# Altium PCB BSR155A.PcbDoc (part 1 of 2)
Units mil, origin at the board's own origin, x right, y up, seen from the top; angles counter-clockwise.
Board outline 3250 x 2500 mil, 4 copper layers (Top Layer, MidLayer1, MidLayer2, Bottom Layer), stack 59.8 mil thick; 70 components, 25 nets, 149 pads, 70 vias.
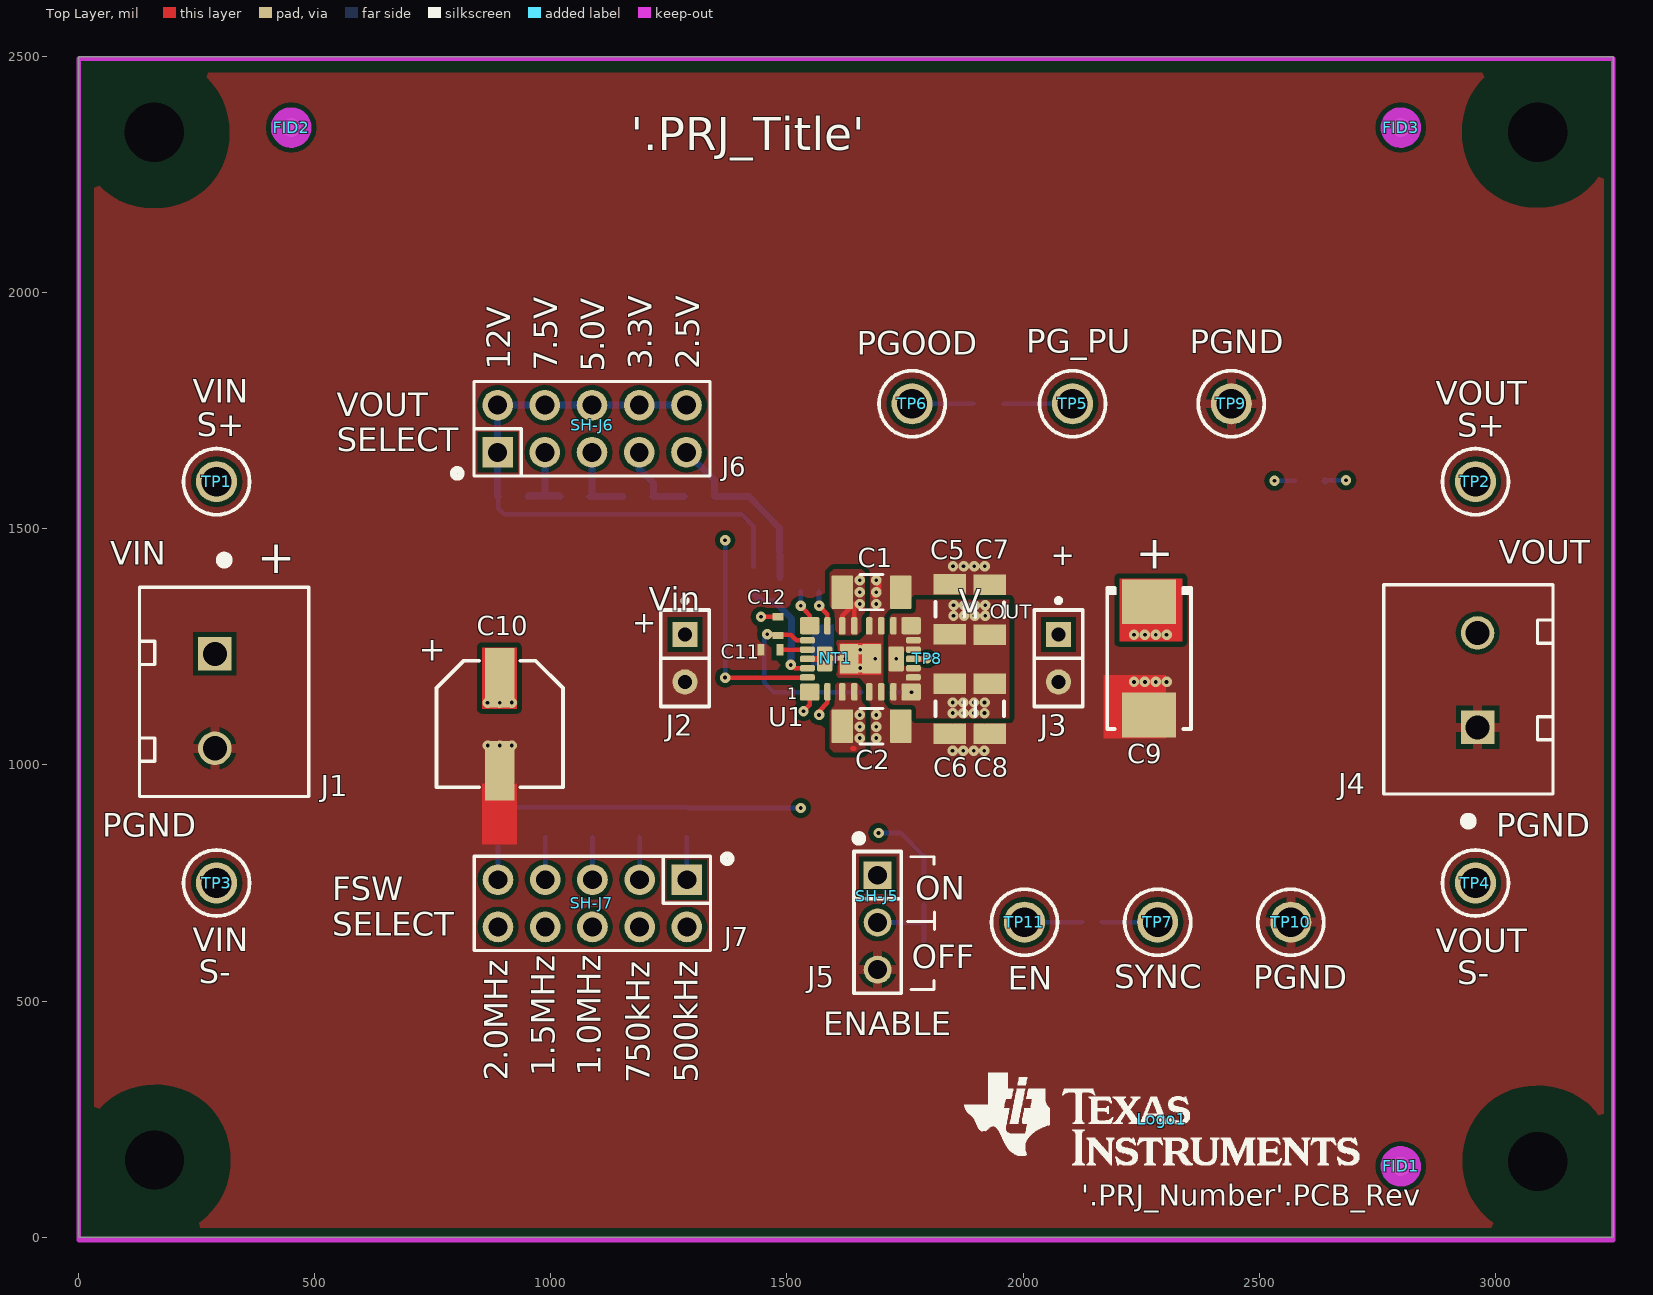
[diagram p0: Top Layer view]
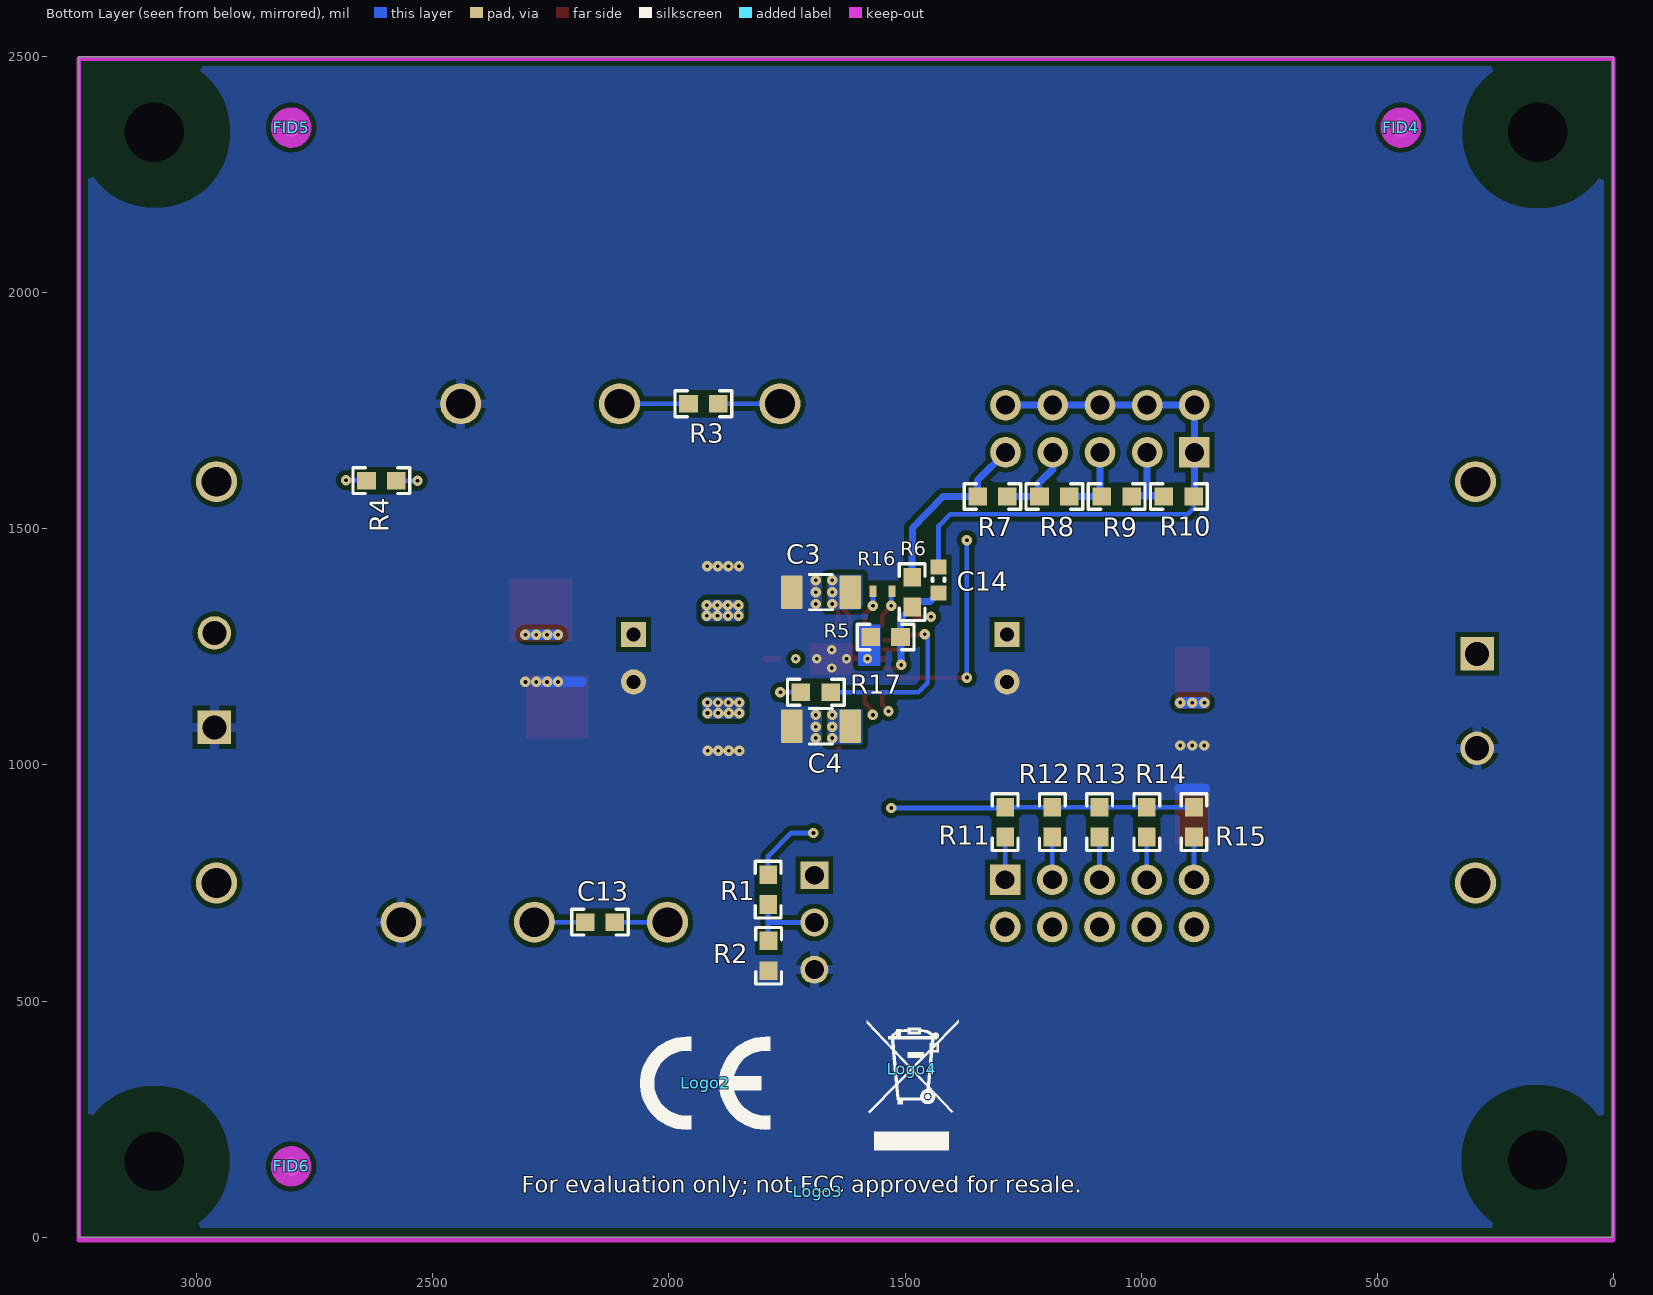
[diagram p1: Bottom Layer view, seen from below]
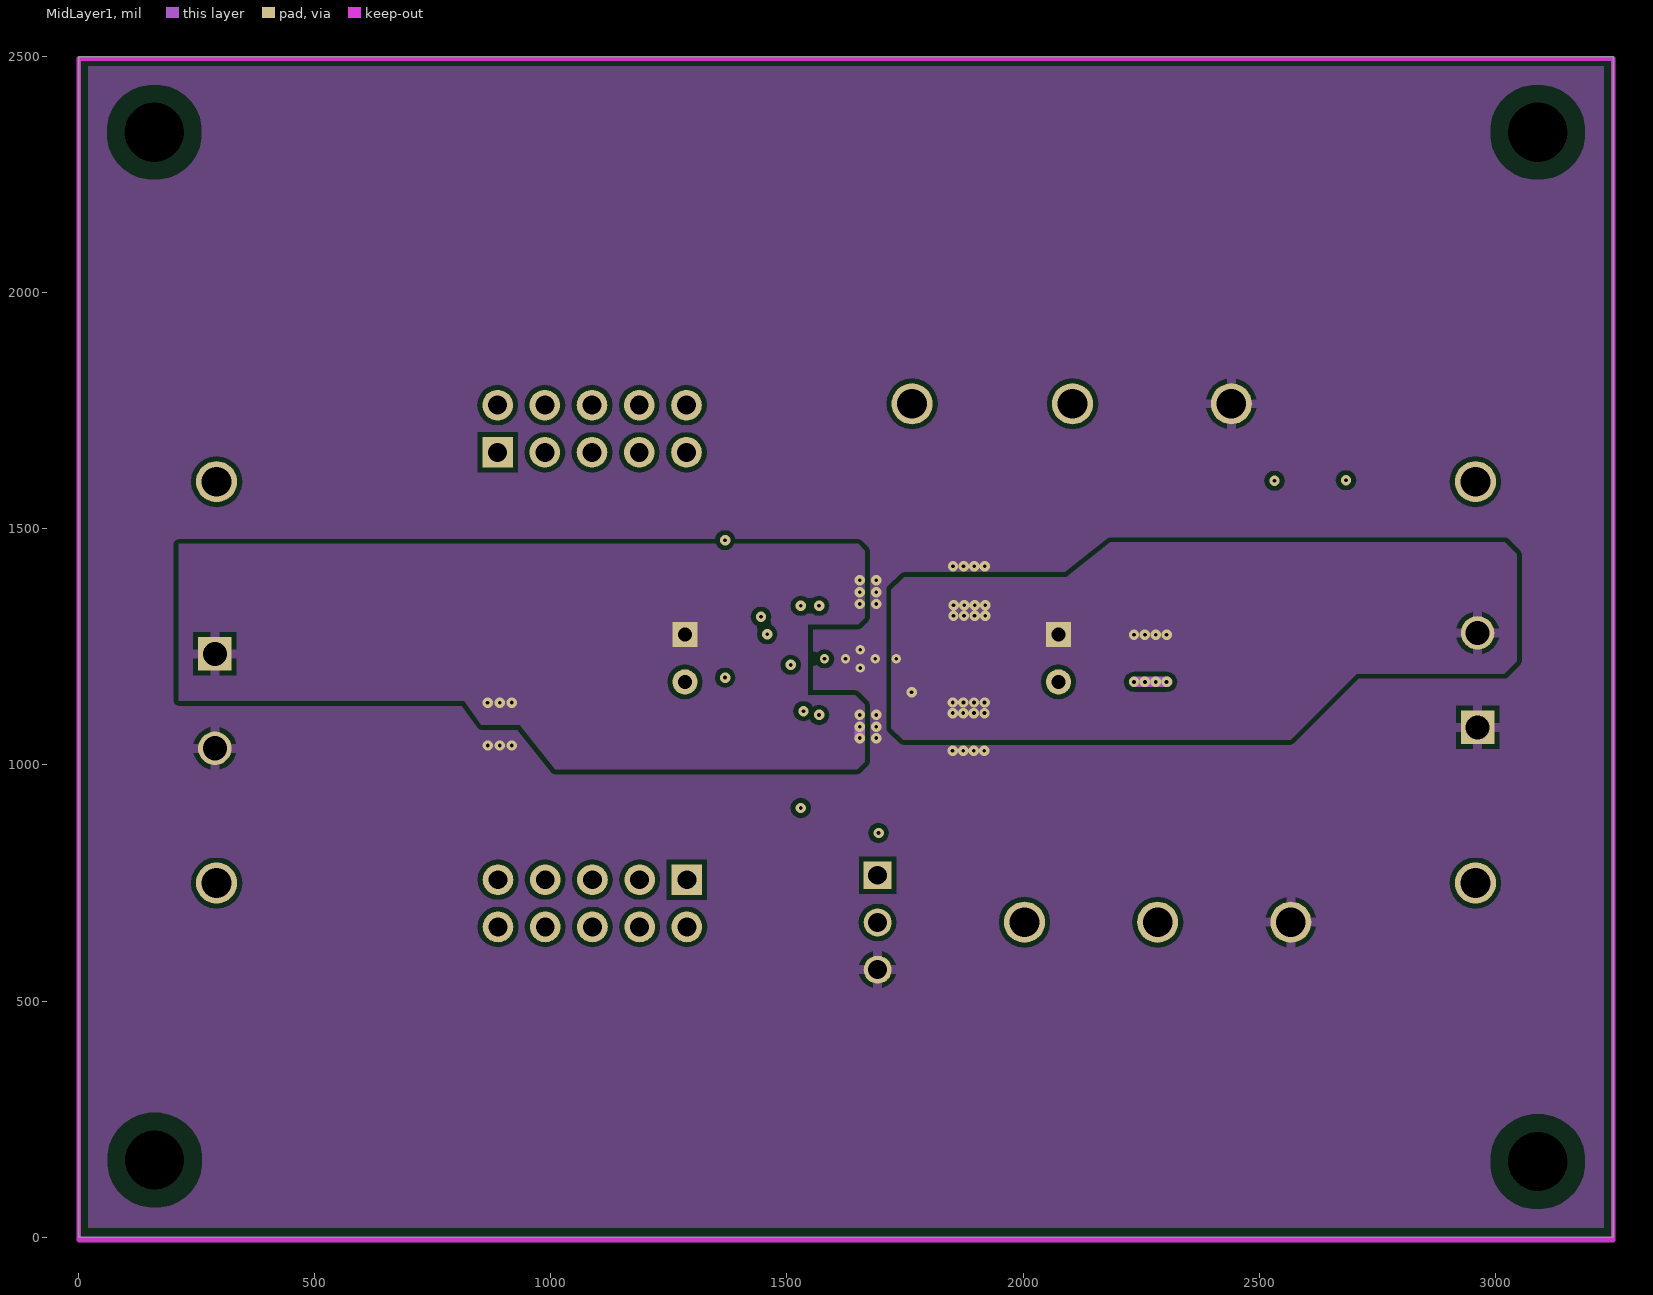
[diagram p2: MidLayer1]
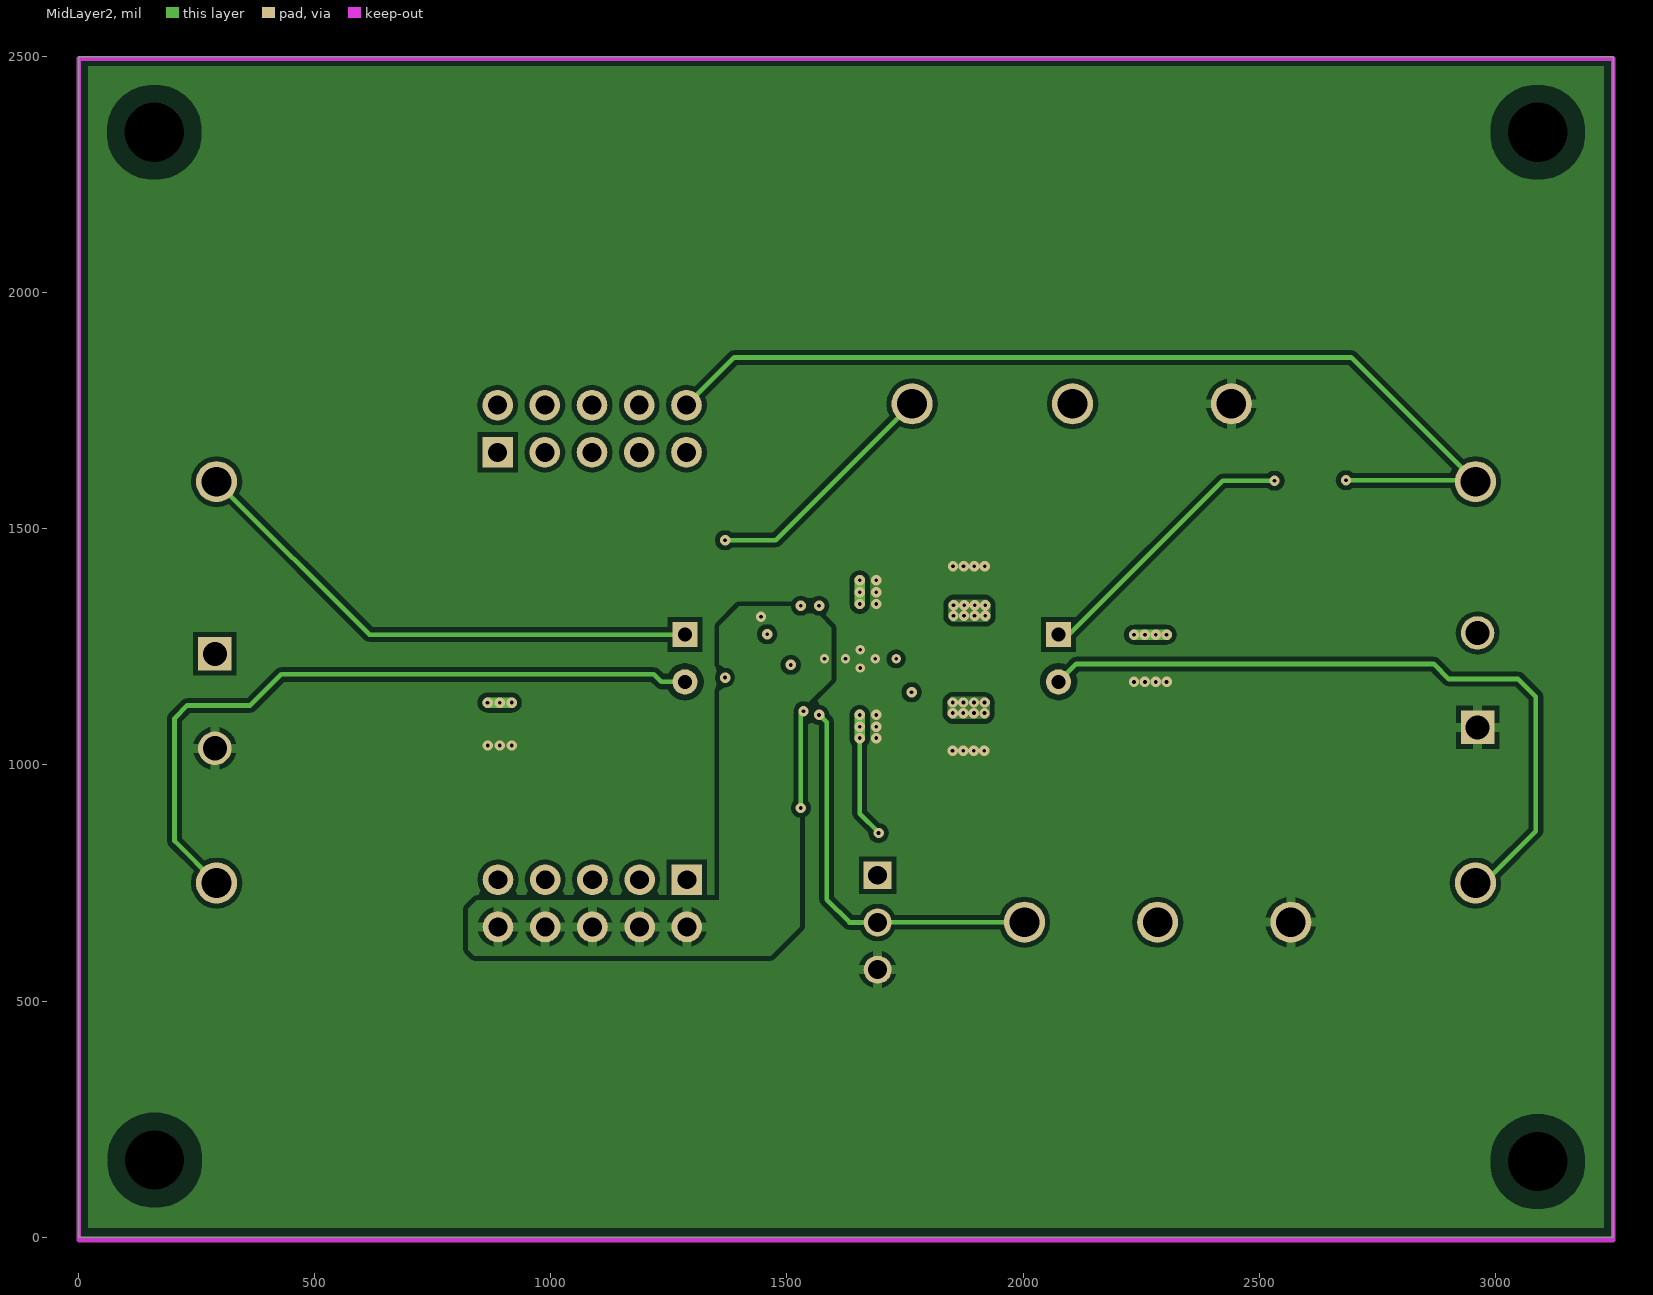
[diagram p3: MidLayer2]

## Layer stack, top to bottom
Top Solder: solder mask 0.4, Solder Resist, Dk 3.5
Top Layer: signal copper 1.4
Dielectric1: prepreg 5, FR-4 High Tg, Dk 4.2
MidLayer1: signal copper 2.8
Dielectric2: core 40, FR-4 High Tg, Dk 4.2
MidLayer2: signal copper 2.8
Dielectric3: prepreg 5, FR-4 High Tg, Dk 4.2
Bottom Layer: signal copper 2.8
Bottom Solder: solder mask 0.4, Solder Resist, Dk 3.5

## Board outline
0,0 0,2500 3250,2500 3250,0

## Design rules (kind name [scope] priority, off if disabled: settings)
AcuteAngle [All] p1: minimum=4.50000000000000E+0001 checktracksonly=TRUE
AssemblyTestPointUsage [All] p1: valid=2
BoardOutlineClearance BoardOutlineClearance_MountingHoles [OnCopper and InComponentClass('Mounting Holes')] p1: gap=40 ignorepadtopadclearanceinfootprint=FALSE
BoardOutlineClearance BoardOutlineClearance_Poly [OnCopper and IsPoly] p2: gap=20 ignorepadtopadclearanceinfootprint=FALSE
BoardOutlineClearance [OnCopper and Not InComponentClass('Logo') and not InComponentClass('FiducialMark') and not InRegion(1000,500,4000,800) and not InPoly] p3: gap=20 ignorepadtopadclearanceinfootprint=FALSE
Clearance Clearance_Keepouts [((IsTrack Or IsArc) And Not InPoly) And IsFree and IsKeepOut vs ((IsTrack Or IsArc) And Not InPoly) And IsFree and IsKeepOut] p1: gap=0 ignorepadtopadclearanceinfootprint=FALSE
Clearance Clearance_Poly [InPolygon] p2: gap=10 ignorepadtopadclearanceinfootprint=FALSE except(0: Arc-Hole Track-Hole SMDPad-Hole THPad-Hole Via-Hole Fill-Hole Poly-Hole Region-Hole Text-Hole)
Clearance Clearance_FiducialMark [IsKeepOut and InComponentClass('FiducialMark') vs IsPad and InComponentClass('FiducialMark')] p3: gap=0 ignorepadtopadclearanceinfootprint=FALSE
Clearance [All] p4: gap=10 ignorepadtopadclearanceinfootprint=FALSE except(0: Arc-Hole Track-Hole SMDPad-Hole THPad-Hole Via-Hole Fill-Hole Poly-Hole Region-Hole Text-Hole; 4: SMDPad-SMDPad; 6: Arc-SMDPad Track-SMDPad SMDPad-THPad; 8: Arc-Arc Arc-Track Track-Track)
ComponentClearance ComponentClearance_MountingHoles_FiducialMarks [InComponentClass('Mounting Holes') vs InComponentClass('FiducialMark')] p1: gap=10 collisioncheckmode=3 verticalgap=10 showdistances=FALSE
ComponentClearance ComponentClearance_Shunt [InComponentClass('Header') vs InComponentClass('Shunt')] p2: gap=0 collisioncheckmode=3 verticalgap=0 showdistances=FALSE
ComponentClearance ComponentClearance_Logo [InComponentClass('Logo')] p3: gap=10 collisioncheckmode=3 verticalgap=10 showdistances=FALSE
ComponentClearance ComponentClearance_ScrewToNut [(HasFootprint('NY PMS 440 0025 PH')) vs (HasFootprint('Keystone_1902C'))] p4: gap=5 collisioncheckmode=3 verticalgap=10 showdistances=FALSE
ComponentClearance ComponentClearance_MountingHoles [InComponentClass('Mounting Holes')] p5: gap=10 collisioncheckmode=3 verticalgap=100000 showdistances=FALSE
ComponentClearance ComponentClearance_SmallPassives [HasFootprint('0201*') or HasFootprint('0402*') or HasFootprint('0508') or HasFootprint('0603*') or HasFootprint('0612') or HasFootprint('0805*') or HasFootprint('0815*') or HasFootprint('0830*') or HasFootprint('1206*') or HasFootprint('1210*') or HasFootprint('1808*') or HasFootprint('1812*') or HasFootprint('1825*') or HasFootprint('2010*') or HasFootprint('2220*') or HasFootprint('2225*') or HasFootprint('2512*') or HasFootprint('2728*') or HasFootprint('3518*') vs HasFootprint('0201*') or HasFootprint('0402*') or HasFootprint('0508') or HasFootprint('0603*') or HasFootprint('0612') or HasFootprint('0805*') or HasFootprint('0815*') or HasFootprint('0830*') or HasFootprint('1206*') or HasFootprint('1210*') or HasFootprint('1808*') or HasFootprint('1812*') or HasFootprint('1825*') or HasFootprint('2010*') or HasFootprint('2220*') or HasFootprint('2225*') or HasFootprint('2512*') or HasFootprint('2728*') or HasFootprint('3518*')] p6: gap=8 collisioncheckmode=3 verticalgap=8 showdistances=FALSE
ComponentClearance ComponentClearance_THtoSMT [IsThruComponent vs IsSMTComponent] p7: gap=10 collisioncheckmode=3 verticalgap=30 showdistances=FALSE
ComponentClearance ComponentClearance_THtoTH [IsThruComponent vs IsThruComponent] p8: gap=10 collisioncheckmode=3 verticalgap=30 showdistances=FALSE
ComponentClearance "ComponentClearance_U1 to NT1" [InComponent('NT1') vs InComponent('U1')] p9: gap=0 collisioncheckmode=3 verticalgap=0 showdistances=FALSE
ComponentClearance [All] p10: gap=10 collisioncheckmode=3 verticalgap=30 showdistances=FALSE
DiffPairsRouting [All] p1: maxlimit=100 minlimit=10 mostfreqgap=10 toplayer_minwidth=15 toplayer_maxwidth=15 toplayer_prefwidth=15 midlayer1_minwidth=15 midlayer1_maxwidth=15 midlayer1_prefwidth=15 midlayer2_minwidth=15 midlayer2_maxwidth=15 midlayer2_prefwidth=15 bottomlayer_minwidth=15 bottomlayer_maxwidth=15 bottomlayer_prefwidth=15 maxuncoupledlength=1000
FabricationTestPointUsage TestPointUsage [All] p1: valid=2 allowmultiple=FALSE
FabricationTestpoint Testpoint [All] p1: side=3 testpointundercomponent=TRUE minsize=40 maxsize=100 preferedsize=60 minholesize=0 maxholesize=40 preferedholesize=32 testpointgrid=1 allowsidetop=TRUE allowsidebottom=TRUE usegrid=TRUE gridtolerance=0.01
FanoutControl Fanout_LCC [IsLCC] p1: bgadir=Out bgaviamode=Centered fanoutstyle=Auto fanoutdirection=Alternating viagrid=1 // Fanout_LCC (Default Rule)
FanoutControl Fanout_BGA [IsBGA] p2: bgadir=Out bgaviamode=Centered fanoutstyle=Auto fanoutdirection=Alternating viagrid=1 // Fanout_BGA (Default Rule)
FanoutControl Fanout_Default [All] p4: bgadir=Out bgaviamode=Centered fanoutstyle=Auto fanoutdirection=Alternating viagrid=1 // Fanout_Default (Default Rule)
FanoutControl Fanout_Small [(CompPinCount < 5)] p5: bgadir=Out bgaviamode=Centered fanoutstyle=Auto fanoutdirection=OutThenIn viagrid=1 // Fanout_Small (Default Rule)
Height [All] p1: minheight=0 maxheight=10000 prefheight=500
HoleSize [All] p1: absolutevalues=TRUE maxlimit=251 minlimit=6 maxpercent=80.000 minpercent=20.000
MinimumAnnularRing MinimumAnnularRing_ThermalPadVias [IsVia and InAnyComponent] p1: minimumring=5
MinimumAnnularRing [All] p2: minimumring=5
MinimumSolderMaskSliver MinimumSolderMaskSliver_1 [HasFootprint('RDA0015A-MFG') vs (InComponent('U1') AND IsVia)] p1: minsoldermaskwidth=1
MinimumSolderMaskSliver MinimumSolderMaskSliver_Logo [InComponentClass('Logo') vs InComponentClass('Logo')] p2: minsoldermaskwidth=0.7
MinimumSolderMaskSliver [All] p3: minsoldermaskwidth=3.94
PlaneClearance PlaneClearance_1 [OnLayer('Top Layer')] p1: clearance=7.87
PlaneClearance [All] p2: clearance=9.84
PlaneConnect PlaneConnect_via [IsVia] p1: planeconnectstyle=Direct reliefexpansion=20 reliefentries=4 reliefconductorwidth=10 reliefairgap=10
PlaneConnect [All] p2: planeconnectstyle=Relief reliefexpansion=10 reliefentries=4 reliefconductorwidth=10 reliefairgap=10
PolygonConnect PolygonConnect_ESD120 [HasFootprint('On-Shore_ED120_2DS')] p1: connectstyle=Relief reliefconductorwidth=25 reliefentries=4 polygonreliefangle="90 Angle" airgapwidth=10
PolygonConnect PolygonConnect_tp [(InComponent('TP*') and not (InComponent('TP9') or InComponent('TP10')))] p2: connectstyle=NoConnect reliefconductorwidth=25 reliefentries=4 polygonreliefangle="90 Angle" airgapwidth=10
PolygonConnect PolygonConnect_logo [InComponent('Logo1')] p3: connectstyle=Direct reliefconductorwidth=10 reliefentries=4 polygonreliefangle="90 Angle" airgapwidth=10
PolygonConnect PolygonConnect_Via [IsVia] p4: connectstyle=Direct reliefconductorwidth=10 reliefentries=4 polygonreliefangle="90 Angle" airgapwidth=10
PolygonConnect PolygonConnect_1 [IsThruPin AND NOT (InComponent('J3') or InComponent('J2'))] p5: connectstyle=Relief reliefconductorwidth=20 reliefentries=4 polygonreliefangle="90 Angle" airgapwidth=10
PolygonConnect PolygonConnect_poly [IsPoly] p6: connectstyle=Direct reliefconductorwidth=10 reliefentries=4 polygonreliefangle="90 Angle" airgapwidth=8
PolygonConnect [All] p7: connectstyle=Relief reliefconductorwidth=10 reliefentries=4 polygonreliefangle="90 Angle" airgapwidth=8
RoutingVias ThermalPadVias [IsVia and InAnyComponent] p1: holewidth=7.87 width=19.68 viastyle="Through Hole" minholewidth=7.87 minwidth=19.68 maxholewidth=12.99 maxwidth=23.62
RoutingVias [All] p2: holewidth=16 width=34 viastyle="Through Hole" minholewidth=6 minwidth=19 maxholewidth=40 maxwidth=65
SilkToBoardRegionClearance SilkToBoardRegionClearance_1 [All] p1:
SilkToSilkClearance SilkToSilkClearance_Pb-FreeLogo [(HasFootprint('Pb-Free_Overlay_Medium') OR HasFootprint('Pb-Free_Overlay_Small')) vs (HasFootprint('Pb-Free_Overlay_Medium') OR HasFootprint('Pb-Free_Overlay_Small'))] p1: silktosilkclearance=0
SilkToSilkClearance [All] p2: silktosilkclearance=3
SilkToSolderMaskClearance "Cap silkscreen on vias" [IsTrack and (InComponent('C1') or InComponent('C11') or InComponent('C12') or InComponent('C2')or InComponent('C5') or InComponent('C6') or InComponent('C7') or InComponent('C8') or InComponent('C13') or InComponent('C14') or InComponent('C15') or InComponent('C16') or InComponent('C11') or InComponent('C12') or InComponent('C3') or InComponent('C4') or InComponent('R1') or InComponent('R2') or InComponent('U1')) vs IsVia] p1: minsilkscreentomaskgap=0 clearancetoexposedcopper=FALSE
SilkToSolderMaskClearance SilkToComponentPadClearance [(IsPad or IsFill or IsRegion) and InAnycomponent] p2: minsilkscreentomaskgap=4.8 clearancetoexposedcopper=TRUE
SilkToSolderMaskClearance "Silk to Solder Mask Opening" [All] p3: minsilkscreentomaskgap=4 clearancetoexposedcopper=FALSE
SolderMaskExpansion [All] p1: expansion=1.97
Width [All] p1: maxlimit=100 minlimit=6 preferedwidth=10 checkconnectedcopper=TRUE
13 further rules are at their usual default settings.

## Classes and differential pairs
component class Shunt: SH-J5 SH-J6 SH-J7
component class Header: J5 J6 J7
component class AssemblyNote: ZZ1 ZZ2 ZZ3 ZZ4 ZZ5 ZZ6
component class FiducialMark: FID1 FID2 FID3 FID4 FID5 FID6
component class Logo: Logo1
component class BSR155A_Hardware: !PCB FID1 FID2 FID3 FID4 FID5 FID6 Logo1 Logo2 Logo3 Logo4 SH-J5 SH-J6 SH-J7 ZZ1 ZZ2 ZZ3 ZZ4 ZZ5 ZZ6
component class BSR155A: C1 C2 C3 C4 C5 C6 C7 C8 C9 C10 C11 C12 C13 C14 C15 J1 J2 J3 J4 J5 J6 J7 NT1 R1 R2 R3 R4 R5 R6 R7 R8 R9 R10 R11 R12 R13 R14 R15 R16 R17 TP1 TP2 TP3 TP4 TP5 TP6 TP7 TP8 TP9 TP10 TP11 U1

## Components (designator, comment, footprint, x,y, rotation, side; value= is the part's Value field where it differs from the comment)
C1 "GRM31CC72A475KE11L" FP-GRM31CC72A475KE11L_1206-MFG 1679,1366 r180 top value=4.7µF
C2 "GRM31CC72A475KE11L" FP-GRM31CC72A475KE11L_1206-MFG 1679,1082 r180 top value=4.7µF
C3 "GRM31CC72A475KE11L" FP-GRM31CC72A475KE11L_1206-MFG 1678,1366 r180 bottom value=4.7µF
C4 "GRM31CC72A475KE11L" FP-GRM31CC72A475KE11L_1206-MFG 1678,1082 r180 bottom value=4.7µF
C5 "C3216X5R1E476M160AC" 1206_190L 1845,1330 r270 top value=47uF
C6 "C3216X5R1E476M160AC" 1206_190L 1845,1118.85 r90 top value=47uF
C7 "C3216X5R1E476M160AC" 1206_190L 1929,1329 r270 top value=47uF
C8 "C3216X5R1E476M160AC" 1206_190L 1929,1119 r90 top value=47uF
C9 "T520Y337M010ATE035" 7343-40 2267,1226 r270 top value=330uF
C10 "EEEFT1H470AP" Panasonic_D 891.6,1086.6 r270 top value=47uF
C11 "EMK105BJ105KVHF" 0402S 1465,1244 r180 top value=1uF
C12 "GRM155R61E105KA12D" 0402S 1481,1294 r90 top value=1uF
C13 "C0603C102J5RACTU" 0603 2146,667 r180 bottom value=1000pF
C14 "GRM188R71C472KA01D" 0603L 1429,1392 r90 bottom value=4700pF
FID1 "Fiducial" Fiducial10-20 2800,150 r0 top
FID2 "Fiducial" Fiducial10-20 450,2350 r0 top
FID3 "Fiducial" Fiducial10-20 2800,2350 r0 top
FID4 "Fiducial" Fiducial10-20 450,2350 r180 bottom
FID5 "Fiducial" Fiducial10-20 2800,2350 r180 bottom
FID6 "Fiducial" Fiducial10-20 2800,150 r180 bottom
J1 "OSTTA024163" On-Shore_OSTTA024163 308,1155 r270 top
J2 "310-43-102-41-001000" Mill-max_310-43-102-41-001000 1284,1226 r270 top
J3 "310-43-102-41-001000" Mill-max_310-43-102-41-001000 2075,1226 r270 top
J4 "OSTTA024163" On-Shore_OSTTA024163 2943,1160 r90 top
J5 "PEC03SAAN" CONN_PEC03SAAN 1692.07,666.47 r270 top
J6 "PEC05DAAN" CONN_PEC05DAAN 1087.13,1712.02 r0 top
J7 "PEC05DAAN" CONN_PEC05DAAN 1088,707 r180 top
Logo1 "Texas Instruments" TI_Stacked_Overlay_Small 2294,250 r0 top
Logo2 "CE Mark" CE_Mark_5mm 1923,326 r180 bottom
Logo3 "FCC disclaimer" FCC_disclaimer 1685,96 r180 bottom
Logo4 "WEEE logo" WEEE_Minimum 1486,356 r180 bottom
NT1 "Net-Tie" Net-Tie_10mil 1602,1226 r0 top net-tie
R1 "CRCW0603402KFKEA" 0603 1790,736 r90 bottom value=402k
R2 "CRCW0603133KFKEA" 0603 1789,596 r90 bottom value=133k
R3 "CRCW060349K9FKEA" 0603 1927,1765 r180 bottom value=49.9k
R4 "CRCW060320R0JNEA" 0603 2609,1602 r0 bottom value=20
R5 "CRCW060310K0FKEA" 0603 1541,1271 r180 bottom value=10.0k
R6 "CRCW060315K0FKEA" 0603 1485,1366 r90 bottom value=15.0k
R7 "CRCW06038K06FKEA" 0603 1314.73,1568.52 r180 bottom value=8.06k
R8 "CRCW060316K9FKEA" 0603 1183.73,1568.52 r180 bottom value=16.9k
R9 "CRCW060324K9FKEA" 0603 1051.73,1568.52 r180 bottom value=24.9k
R10 "CRCW060345K3FKEA" 0603 920.13,1568.52 r180 bottom value=45.3k
R11 "CRCW060326K7FKEA" 0603 1288,879 r90 bottom value=26.7k
R12 "CRCW060317K4FKEA" 0603 1188,879 r90 bottom value=17.4k
R13 "CRCW060313K0FKEA" 0603 1088,879 r90 bottom value=13.0k
R14 "CRCW06038K66FKEA" 0603 988,879 r90 bottom value=8.66k
R15 "CRCW06036K34FKEA" 0603 888,879 r90 bottom value=6.34k
R16 "CRCW040210R0JNED" 0402S 1548,1368 r0 bottom value=10
R17 "RMCF0603ZT0R00" 0603 1689,1154 r180 bottom value=0
SH-J5 "2SN-BK-G" 2SN-BK-G 1691,722 r90 top value=1x2
SH-J6 "2SN-BK-G" 2SN-BK-G 1087.13,1719.17 r90 top value=1x2
SH-J7 "2SN-BK-G" 2SN-BK-G 1086.42,707.11 r90 top value=1x2
TP1 "5010" Keystone5010 292,1600 r90 top
TP2 "5010" Keystone5010 2958,1600 r90 top
TP3 "5011" Keystone5011 292,750 r90 top
TP4 "5011" Keystone5011 2958,750 r90 top
TP5 "5012" Keystone5012 2104.73,1765 r180 top
TP6 "5012" Keystone5012 1765,1765 r180 top
TP7 "5012" Keystone5012 2285,667 r0 top
TP8 "TESTPOINT" TP_25MIL-SMT 1797,1225 r90 top
TP9 "5011" Keystone5011 2441,1765 r0 top
TP10 "5011" Keystone5011 2567,667 r0 top
TP11 "5012" Keystone5012 2003,667 r0 top
U1 "TPSM63603RDHR" RDH0030A-MFG 1655.45,1224.74 r90 top
ZZ1 "These assemblies are ESD sensitive, ESD precautions shall be observed." AssemblyNote -430,3004 r0 top
ZZ2 "These assemblies must be clean and free from flux and all contaminants. Use of no clean flux is not acceptable." AssemblyNote -430,3188 r0 top
ZZ3 "These assemblies must comply with workmanship standards IPC-A-610 Class 2, unless otherwise specified." AssemblyNote -430,3371 r0 top
ZZ4 "Place SH-J5 on J5 pins 2 and 3" AssemblyNote -425,3544 r0 top
ZZ5 "Place SH-J6 on J6 pins 5 and 6" AssemblyNote -434,3678 r0 top
ZZ6 "Place SH-J7 on J7 pins 5 and 6" AssemblyNote -434,3810 r0 top

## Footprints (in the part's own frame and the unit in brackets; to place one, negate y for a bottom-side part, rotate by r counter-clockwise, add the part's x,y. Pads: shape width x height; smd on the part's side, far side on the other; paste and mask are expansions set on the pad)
2SN-BK-G [mil] "Samtec STEP model"
  round 1 on Mech3: 0(0,0)
  body extent -78,-39 79,39, height 188
0402S [mil] "Based on C0402S footprint from PADS legacy"
  rect 15x24 smd: 1(-20,0) 2(20,0)
  body extent -22,-12 22,12, height 24
0603 [mm] "0603 from SM-752 data"
  rect 1x0.95 smd: 1(-0.8,0) 2(0.8,0)
  silkscreen extent -1.52,-0.69 1.52,0.69, body extent -0.87,-0.47 0.87,0.47, height 1
0603L [mm] "0603 from SM-752 data"
  rect 0.8x0.85 smd: 1(-0.7,0) 2(0.7,0)
  silkscreen extent -0.07,-0.33 0.07,0.33, body extent -0.87,-0.47 0.87,0.47, height 1
1206_190L [mm] "1206_190"
  rect 1.1x1.75 smd: 1(-1.35,0) 2(1.35,0)
  silkscreen extent -0.4,-0.77 0.4,0.77, body extent -1.75,-0.95 1.75,0.95, height 1.9
7343-40 [mm] "Molded, 2-Leads, Body 7.3x4.3mm, Height 4mm"
  rect 2.4x2.9 smd: 1(-3.05,0) 2(3.05,0)
  silkscreen extent -3.8,-2.25 3.8,2.25, body extent -3.8,-2.25 3.8,2.25, height 4.01
AssemblyNote [mil] "Assembly Note"
CE_Mark_5mm [mil] "Minimum text height for CE Mark"
  silkscreen extent -138,-98 138,98
CONN_PEC03SAAN [mm] "SULLINS"
  rect 1.5x1.5 hole 1.016: 1(-2.54,0)
  round 1.5 hole 1.016: 2(0,0) 3(2.54,0)
  silkscreen extent -4.72,-1.27 3.81,1.27, body extent -3.84,-1.3 3.84,1.3, height 8.38
CONN_PEC05DAAN [mm] "SULLINS"
  rect 1.65x1.65 hole 1.016 mask+0: 1(-5.08,-1.27)
  round 1.65 hole 1.016 mask+0: 2(-5.08,1.27) 3(-2.54,-1.27) 4(-2.54,1.27) 5(0,-1.27) 6(0,1.27) 7(2.54,-1.27) 8(2.54,1.27) 9(5.08,-1.27) 10(5.08,1.27)
  silkscreen extent -7.45,-2.6 6.35,2.54, body extent -6.35,-2.54 6.35,2.54, height 8.38
FCC_disclaimer [mil]
Fiducial10-20 [mm]
  round 1 smd mask+0.5: 1(0,0)
  Top Layer keep-out circle w1.178: c0,0 r0.5
FP-GRM31CC72A475KE11L_1206-MFG [mm]
  rrect9% 1.15x1.8 smd paste+0 mask+0: 1(-1.575,0) 2(1.575,0)
  silkscreen extent -0.63,-0.95 0.63,0.95, body extent -2.25,-1.05 2.25,1.05, height 0.25
Keystone5010 [mil] "Keystone Multipurpose loops"
  round 87 hole 63: 1(0,0)
  silkscreen extent -70,-70 70,70, body extent -63,-63 63,62, height 319
Keystone5011 [mil] "Keystone Multipurpose loops"
  round 87 hole 63: 1(0,0)
  silkscreen extent -70,-70 70,70, body extent -63,-63 63,62, height 319
Keystone5012 [mil] "Keystone Multipurpose loops"
  round 87 hole 63: 1(0,0)
  silkscreen extent -70,-70 70,70, body extent -63,-63 63,62, height 319
Mill-max_310-43-102-41-001000 [mm] "Mill-max"
  rect 1.35x1.35 hole 0.75: 1(-1.27,0)
  round 1.35 hole 0.75: 2(1.27,0)
  silkscreen extent -3.22,-1.3 2.6,1.3, body extent -2.55,-1.27 2.55,1.27, height 4.22
Net-Tie_10mil [mil] "10mil net tie, no solder mask opening, no solder paste"
  rect 10x10 smd paste-5 mask-5: 1(-10,0) 2(10,0)
  Top Layer region: -6,5 6,5 6,-5 -6,-5
On-Shore_OSTTA024163 [mm] "TERM BLOCK 2x1, 5.08mm, TH"
  rect 1.8x1.8 hole 1.3: 1(-2.04,-0.5)
  round 1.8 hole 1.3 paste+0: 2(3.04,-0.5)
  silkscreen extent -7.18,-4.55 5.63,4.55, body extent -5.68,-4.6 5.68,4.6, height 13
Panasonic_D [mm] "SMD, 2-Leads, Dia 6.3mm"
  rect 3.2x1.6 smd: 1(-2.5,0) 2(2.5,0)
  silkscreen extent -3.4,-3.4 3.4,3.4, body extent -3.4,-3.4 3.4,3.4, height 6.11
RDH0030A-MFG [mm]
  rrect22% 0.93x1.05 smd paste-1000 mask-1000: 1(-1.786,2.725) 8(-1.786,-2.725) 14(1.786,-2.725) 21(1.786,2.725)
  rrect57% 0.95x0.35 smd paste-1000 mask-1000: 2(-1.775,1.775) 3(-1.775,0.975) 4(-1.775,0.325) 5(-1.775,-0.475) 6(-1.775,-1.125) 7(-1.775,-1.775) 15(1.775,-1.775) 16(1.775,-1.125) 17(1.775,-0.475) 18(1.775,0.325) 19(1.775,0.975) 20(1.775,1.775)
  rrect57% 0.35x0.8 smd paste-1000 mask-1000: 9(-1,-2.85) 10(-0.5,-2.85) 11(0,-2.85) 12(0.5,-2.85) 13(1,-2.85) 22(1,2.85) 23(0.5,2.85) 24(0,2.85) 25(-0.5,2.85) 26(-1,2.85)
  rrect24% 1.35x0.84 smd paste-1000 mask-1000: 27(0,1.925) 30(0,-1.925)
  rrect10% 1.6x1 smd paste-1000 mask-1000: 28(0,0.6) 29(0,-0.6)
  Top Layer region: -0.85,1.05 -0.837,1.1 -0.8,1.137 -0.75,1.15 -0.75,1.15 0.75,1.15 0.8,1.137 0.837,1.1 0.85,1.05 0.85,1.05 0.85,-1.05 0.837,-1.1 0.8,-1.137 0.75,-1.15 0.75,-1.15 -0.75,-1.15 -0.8,-1.137 -0.837,-1.1 -0.85,-1.05 -0.85,-1.05
  body extent -2.35,-3.35 2.35,3.35, height 0.25
TI_Stacked_Overlay_Small [mil]
  silkscreen extent -418,-98 418,98
TP_25MIL-SMT [mil]
  round 20 smd mask-2.5: 1(0,0)
WEEE_Minimum [mil] "WEEElie bin"
  silkscreen extent -95,-172 99,104

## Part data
C1 C2 C3 C4: library part CMP-0089881-1, "4.7µF ±10% 100V Ceramic Capacitor X7S 1206 (3216 Metric)", Digikey Part Number=490-18620-1-ND, Manufacturer=Murata, Mouser Part Number=81-GRM31CC72A475KE1L, Operating Temperature Range="-55°C to +125°C", TempCo=22%, Temperature Characteristic=X7S, Tolerance_%=10%, ValueDisplayed=4.7uF
C5 C6 C7 C8: library part CMP-0008656-2, "CAP, CERM, 47 uF, 25 V, +/- 20%, X5R, 1206_190", Cap_Case=1206, Manufacturer=TDK, Supplier Part Number 1=445-8047-1-ND, TempCo=X5R, Tolerance_%=20%, Value1=Unknown, Value2=25V, ValueDisplayed=47uF
C9: library part CMP-0064986-2, "CAP, Tantalum Polymer, 330 uF, 10 V,+/- 20%, 0.035 ohm, 7343-40 SMD", Cap_Case=7343-40, Manufacturer=Kemet, Supplier Part Number 1=399-10363-1-ND, Tolerance_%=20%, Value1="0.035 ohm", Value2=10V, ValueDisplayed=330uF
C10: library part CMP-0011204-2, "CAP, AL, 47 uF, 50 V, +/- 20%, 0.68 ohm, AEC-Q200 Grade 2, SMD", Cap_Case=6.3x5.8mm, Manufacturer=Panasonic, Supplier Part Number 1=PCE5023CT-ND, Tolerance_%=20%, Value1="0.68 ohm", Value2=50V, ValueDisplayed=47uF
C11: library part CMP-0006347-2, "CAP, CERM, 1 uF, 16 V, +/- 10%, X5R, 0402", Cap_Case=0402, Manufacturer="Taiyo Yuden", Supplier Part Number 1=587-3709-2-ND, TempCo=X5R, Tolerance_%=10%, Value1=Unknown, Value2=16V, ValueDisplayed=1uF
C12: library part CMP-0006608-2, "CAP, CERM, 1 uF, 25 V, +/- 10%, X5R, 0402", Cap_Case=0402, Manufacturer=MuRata, Supplier Part Number 1=490-10017-1-ND, TempCo=X5R, Tolerance_%=10%, Value1=Unknown, Value2=25V, ValueDisplayed=1uF
C13: library part CMP-0006845-4, "CAP, CERM, 1000 pF, 50 V, +/- 5%, X7R, 0603", Cap_Case=0603, Manufacturer=Kemet, Supplier Part Number 1=399-1083-1-ND, TempCo=X7R, Tolerance_%=5%, Value1=Unknown, Value2=50V, ValueDisplayed=1000pF
C14: library part CMP-0007396-4, "CAP, CERM, 4700 pF, 16 V, +/- 10%, X7R, 0603", Cap_Case=0603, Manufacturer=MuRata, Supplier Part Number 1=GRM188R71C472KA01D-ND, TempCo=X7R, Tolerance_%=10%, Value1=Unknown, Value2=16V, ValueDisplayed=4700pF
FID1 FID2 FID3 FID4 FID5 FID6: library part CMP-0077181-1, "Fiducial mark.  There is nothing to buy or mount.", Manufacturer=N/A
J1 J4: library part CMP-0074959-1, "Terminal Block, 2x1, 5.08mm, TH", Manufacturer="On-Shore Technology", Supplier Part Number 1=ED2580-ND
J2 J3: library part CMP-0055017-1, "Socket Strip, 2x1, 100mil, Black, Tin, TH", Manufacturer=Mill-Max, Supplier Part Number 1=ED6202-ND
J5: library part CMP-0002338-1, "Header, 100mil, 3x1, Tin, TH", Color=Black, Current_A=3A, Manufacturer="Sullins Connector Solutions", Supplier Part Number 1=S1012E-03-ND, Voltage_V=1.8kV
J6 J7: library part CMP-0054550-2, "Header, 100mil, 5x2, Tin, TH", Color=Black, Current_A=3A, Manufacturer="Sullins Connector Solutions", Supplier Part Number 1=S2012E-05-ND, Voltage_V=1.8kV
Logo1: library part CMP-0074838-1, "Texas Instrument Corporate Signature"
Logo2: library part CMP-0074844-1
Logo3: library part CMP-0074847-1, "FCC_disclaimer"
Logo4: library part CMP-0074769-1
NT1: library part CMP-0078142-3, "Single point connection between nets.", Manufacturer=N/A
R1: library part CMP-0022408-4, "RES, 402 k, 1%, 0.1 W, AEC-Q200 Grade 0, 0603", Manufacturer=Vishay-Dale, Power_W=100mW, Supplier Part Number 1=541-402KHCT-ND, TempCo="100 ppm/C", Tolerance_%=1%, Value2=0.1W, Value_Code=402k
R2: library part CMP-0022038-4, "RES, 133 k, 1%, 0.1 W, AEC-Q200 Grade 0, 0603", Manufacturer=Vishay-Dale, Power_W=100mW, Supplier Part Number 1=541-133KHCT-ND, TempCo="100 ppm/C", Tolerance_%=1%, Value2=0.1W, Value_Code=133k
R3: library part CMP-0022447-4, "RES, 49.9 k, 1%, 0.1 W, AEC-Q200 Grade 0, 0603", Manufacturer=Vishay-Dale, Power_W=100mW, Supplier Part Number 1=541-49.9KHCT-ND, TempCo="100 ppm/C", Tolerance_%=1%, Value2=0.1W, Value_Code=49k9, ValueDisplayed=49.9k
R4: library part CMP-0025754-4, "RES, 20, 5%, 0.1 W, AEC-Q200 Grade 0, 0603", Manufacturer=Vishay-Dale, Power_W=100mW, Supplier Part Number 1=541-20GCT-ND, TempCo="200 ppm/C", Tolerance_%=5%, Value2=0.1W, Value_Code=20R0, ValueDisplayed=20
R5: library part CMP-0021998-4, "RES, 10.0 k, 1%, 0.1 W, AEC-Q200 Grade 0, 0603", Manufacturer=Vishay-Dale, Power_W=100mW, Supplier Part Number 1=541-10.0KHCT-ND, TempCo="100 ppm/C", Tolerance_%=1%, Value2=0.1W, Value_Code=10k0, ValueDisplayed=10.0k
R6: library part CMP-0022066-4, "RES, 15.0 k, 1%, 0.1 W, AEC-Q200 Grade 0, 0603", Manufacturer=Vishay-Dale, Power_W=100mW, Supplier Part Number 1=541-15.0KHCT-ND, TempCo="100 ppm/C", Tolerance_%=1%, Value2=0.1W, Value_Code=15k0, ValueDisplayed=15.0k
R7: library part CMP-0022634-4, "RES, 8.06 k, 1%, 0.1 W, AEC-Q200 Grade 0, 0603", Manufacturer=Vishay-Dale, Power_W=100mW, Supplier Part Number 1=541-8.06KHCT-ND, TempCo="100 ppm/C", Tolerance_%=1%, Value2=0.1W, Value_Code=8k06, ValueDisplayed=8.06k
R8: library part CMP-0022081-4, "RES, 16.9 k, 1%, 0.1 W, AEC-Q200 Grade 0, 0603", Manufacturer=Vishay-Dale, Power_W=100mW, Supplier Part Number 1=541-16.9KHCT-ND, TempCo="100 ppm/C", Tolerance_%=1%, Value2=0.1W, Value_Code=16k9, ValueDisplayed=16.9k
R9: library part CMP-0022237-4, "RES, 24.9 k, 1%, 0.1 W, AEC-Q200 Grade 0, 0603", Manufacturer=Vishay-Dale, Power_W=100mW, Supplier Part Number 1=541-24.9KHCT-ND, TempCo="100 ppm/C", Tolerance_%=1%, Value2=0.1W, Value_Code=24k9, ValueDisplayed=24.9k
R10: library part CMP-0022430-4, "RES, 45.3 k, 1%, 0.1 W, AEC-Q200 Grade 0, 0603", Manufacturer=Vishay-Dale, Power_W=100mW, Supplier Part Number 1=541-45.3KHCT-ND, TempCo="100 ppm/C", Tolerance_%=1%, Value2=0.1W, Value_Code=45k3, ValueDisplayed=45.3k
R11: library part CMP-0022249-4, "RES, 26.7 k, 1%, 0.1 W, AEC-Q200 Grade 0, 0603", Manufacturer=Vishay-Dale, Power_W=100mW, Supplier Part Number 1=541-26.7KHCT-ND, TempCo="100 ppm/C", Tolerance_%=1%, Value2=0.1W, Value_Code=26k7, ValueDisplayed=26.7k
R12: library part CMP-0022089-4, "RES, 17.4 k, 1%, 0.1 W, AEC-Q200 Grade 0, 0603", Manufacturer=Vishay-Dale, Power_W=100mW, Supplier Part Number 1=541-17.4KHCT-ND, TempCo="100 ppm/C", Tolerance_%=1%, Value2=0.1W, Value_Code=17k4, ValueDisplayed=17.4k
R13: library part CMP-0022042-4, "RES, 13.0 k, 1%, 0.1 W, AEC-Q200 Grade 0, 0603", Manufacturer=Vishay-Dale, Power_W=100mW, Supplier Part Number 1=541-13.0KHCT-ND, TempCo="100 ppm/C", Tolerance_%=1%, Value2=0.1W, Value_Code=13k0, ValueDisplayed=13.0k
R14: library part CMP-0022637-4, "RES, 8.66 k, 1%, 0.1 W, AEC-Q200 Grade 0, 0603", Manufacturer=Vishay-Dale, Power_W=100mW, Supplier Part Number 1=541-8.66KHCT-ND, TempCo="100 ppm/C", Tolerance_%=1%, Value2=0.1W, Value_Code=8k66, ValueDisplayed=8.66k
R15: library part CMP-0022560-4, "RES, 6.34 k, 1%, 0.1 W, AEC-Q200 Grade 0, 0603", Manufacturer=Vishay-Dale, Power_W=100mW, Supplier Part Number 1=541-6.34KHCT-ND, TempCo="100 ppm/C", Tolerance_%=1%, Value2=0.1W, Value_Code=6k34, ValueDisplayed=6.34k
R16: library part CMP-0026827-3, "RES, 10, 5%, 0.063 W, AEC-Q200 Grade 0, 0402", Manufacturer=Vishay-Dale, Power_W=63mW, Supplier Part Number 1=541-10JCT-ND, TempCo="200 ppm/C", Tolerance_%=5%, Value2=0.063W, Value_Code=10R0, ValueDisplayed=10
R17: library part CMP-0023343-3, "RES, 0, 1%, 0.1 W, AEC-Q200 Grade 0, 0603", Manufacturer="Stackpole Electronics Inc", Power_W=100mW, Supplier Part Number 1=RMCF0603ZT0R00CT-ND, TempCo=ppm/C, Tolerance_%=1%, Value2=0.1W, Value_Code=0
SH-J5 SH-J6 SH-J7: library part CMP-0003641-1, "Shunt, 2mm, Gold plated, Black", Manufacturer=Samtec, Supplier Part Number 1=SAM8748-ND
TP1 TP2: library part CMP-0055147-1, "Test Point, Multipurpose, Red, TH", Color=Red, Manufacturer=Keystone, Supplier Part Number 1=36-5010-ND
TP3 TP4 TP9 TP10: library part CMP-0055148-1, "Test Point, Multipurpose, Black, TH", Color=Black, Manufacturer=Keystone, Supplier Part Number 1=36-5011-ND
TP5 TP6 TP7 TP11: library part CMP-0055149-1, "Test Point, Multipurpose, White, TH", Color=White, Manufacturer=Keystone, Supplier Part Number 1=36-5012-ND
TP8: library part CMP-0078143-3, "TEST POINT.  No entry in BOM.", Manufacturer=N/A
U1: library part CMP-0090663-2, "TPSM63603 Cruzline Power Module", Manufacturer="Texas Instruments", Max Supply Voltage=36V, Min Supply Voltage=3V, Nominal Supply Current=9uA, Operating Temperature Range="-40°C to +125°C", Output Voltage=1-12V, Switching Frequency=200-2200kHz
ZZ1: library part CMP-0077236-1
ZZ2: library part CMP-0077237-1
ZZ3: library part CMP-0077238-1
ZZ4 ZZ5 ZZ6: library part CMP-0003615-1, "This Assembly Note will show in the PcbDoc and associated outputs"

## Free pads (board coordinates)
  round 120 hole 125 unplated: 0(160,2340) 0(161,163) 0(3090,160) 0(3090,2340)

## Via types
v1: diameter 22, hole 8, Top Layer to Bottom Layer, 64 vias
v2: diameter 19.68, hole 7.87, Top Layer to Bottom Layer, 6 vias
